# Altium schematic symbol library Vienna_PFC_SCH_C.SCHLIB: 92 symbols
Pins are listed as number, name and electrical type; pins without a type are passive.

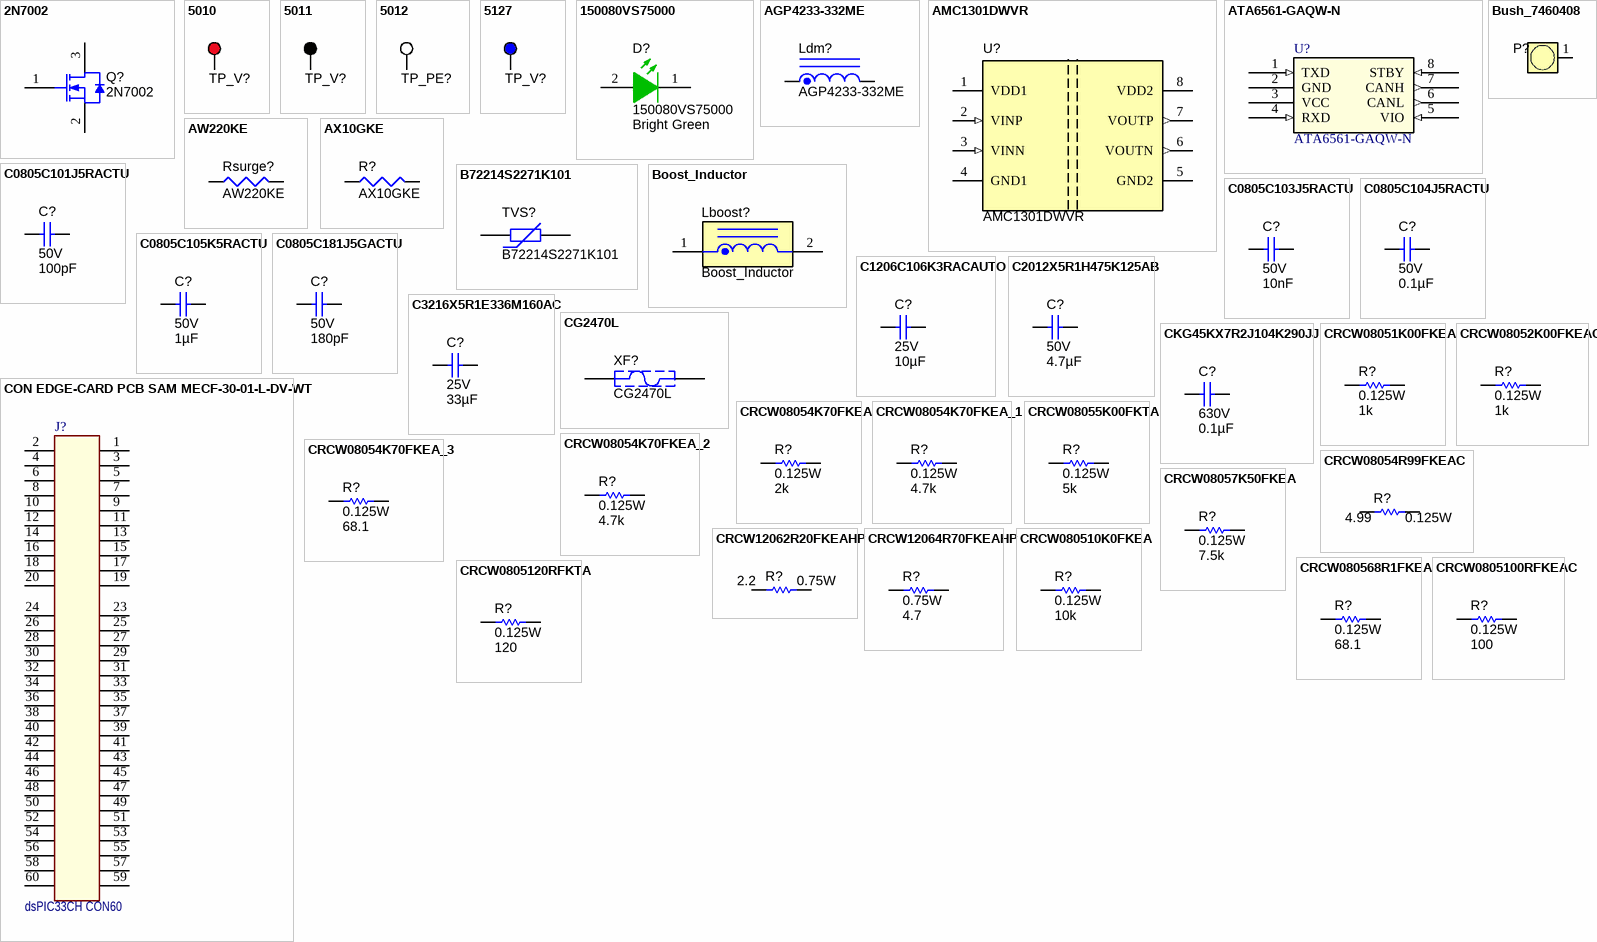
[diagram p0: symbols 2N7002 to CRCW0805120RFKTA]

## 2N7002
designator Q?
MOSFET, N-CH, 60 V, 115 MA, SOT-23; Manufacturer: Fairchild Semiconductor; Alternate Manufacturer: None; U/M: EA; ChType: N; Value: 60V; VdsMax_V: 60; Value1: ? ohm; Value2: ? nC; Vgs_V: 20; IdsMax_A: 115; SizeAreaWB_mm2: 14; SizeArea_mm2: 7.5; SizeX_mm: 2.5; SizeY_mm: 3; SizeZ_mm: 1.1; AEC Category: Q101
footprint SOT-23 (SOT23, 3-Leads, Body 2.9x1.3mm, Pitch 0.95mm, Lead Span 2.5mm, IPC Medium Density)
footprint SOT-23M
footprint SOT-23L
pins: 1 G, 2 S, 3 D

## 5010
designator TP_V?  (value not drawn)
Test Point, Multipurpose, Red, TH; Manufacturer: Keystone; CompType: Test Point Loop; ContactFinish: Silver
footprint Keystone5010 (Keystone Multipurpose loops)
pins: 1

## 5011
designator TP_V?  (value not drawn)
Test Point, Multipurpose, Black, TH; Manufacturer: Keystone; CompType: Test Point Loop; ContactFinish: Silver
footprint Keystone5011 (Keystone Multipurpose loops)
pins: 1

## 5012
designator TP_PE?  (value not drawn)
Test Point, Multipurpose, White, TH; Manufacturer: Keystone; CompType: Test Point Loop; ContactFinish: Silver
footprint Keystone5012 (Keystone Multipurpose loops)
pins: 1

## 5127
designator TP_V?  (value not drawn)
Test Point, Multipurpose, Blue, TH; Manufacturer: Keystone; CompType: Test Point Loop; U/M: EA; ContactFinish: Silver
footprint Keystone5127 (Keystone Multipurpose loops)
pins: 1

## 150080VS75000
designator D?  value Bright Green
LED, Bright Green, SMD; Manufacturer: Wurth Elektronik; SymbolCreator: Altium; Type: AlInGaP; Vf_V: 2; Value2: 2V; Io_A: 0.02; Vr_V: 5; Tjmax_C: 85; Power_TotalModule: 0.072; Value1: 0.072W; Angle: 140; U/M: EA
footprint WL-SMCW_Green_0805 (SMD, 2-Leads, Body 2x1.25mm)
pins: 1 K, 2 A

## AGP4233-332ME
designator Ldm?
FIXED IND 3.3UH 34A  TH, Coilcraft; CompType: Fixed Inductors
footprint AGP4233-332ME (Inductor)
pins: 1, 2

## AMC1301DWVR
designator U?
Precision +/-250-mV Input, 3-us Delay, Reinforced Isolated Amplifier, DWV0008A (SOIC-8); Manufacturer: Texas Instruments; SymbolCreator: Altium; SizeArea_mm2: 67.275; SizeAreaWB_mm2: 105.975; SizeX_mm: 11.5; SizeY_mm: 5.85; SizeZ_mm: 2.8; CompType: IC; U/M: EA
footprint AMC1301 (SOIC, 8-Leads, Body 5.95x7.6mm (max), Pitch 1.27mm)
pins: 1 VDD1 (power), 2 VINP (in), 3 VINN (in), 4 GND1 (power), 5 GND2 (power), 6 VOUTN (out), 7 VOUTP (out), 8 VDD2 (power)

## ATA6561-GAQW-N
designator U?
CAN Interface IC Industrial Grade CAN TRX with VIO PIN (SO8); Manufacturer: Microchip Technology / Atmel; GENERIC_PART_NUMBER: SN65HVD234; INDUSTRY_STD_PKG_TYPE: SOIC; PIN_COUNT: 8; PACKAGE_DESIGNATOR: D; Vendor: Mouser
footprint SOIC8
pins: 1 TXD (in), 2 GND (power), 3 VCC (power), 4 RXD (in), 5 VIO (in), 6 CANL (out), 7 CANH (out), 8 STBY (in)

## AW220KE
designator Rsurge?
RES 22 OHM 2.5W 10% RADIAL; Manufacturer: Ohmite; CompType: Through Hole Resistors
footprint AW220KE (Capacitor)
pins: 1, 2

## AX10GKE
designator R?
RES 1 OHM 3.5W 10% RADIAL; Manufacturer: Ohmite; CompType: Through Hole Resistors
footprint AX10GKE (Res)
pins: 1, 2

## B72214S2271K101
designator TVS?
VARISTOR 430V 6KA DISC 14MM, EPCOS (TDK); CompType: TVS - Varistors, MOVs
footprint B72214S2271K101 (Capacitor)
pins: 1, 2

## Boost_Inductor
designator Lboost?
Boost_Inductor, Handmake
footprint Boost_Inductor
pins: 1, 2

## Bush_7460408
designator P?  (value not drawn)
TERM PWR ELEMENT M5 12 PIN PCB; Manufacturer: Wurth Electronics Inc.
footprint Bush7460408 (Power Connecter 12pin)
pins: 1 (power) "Voltage input"

## C0805C101J5RACTU
designator C?  VDC_V: 50V  ValueDisplayed: 100pF  (hidden comment: C0805C101J5RACTU)
CAP, CERM, 100 pF, 50 V, +/- 5%, X7R, 0805; Manufacturer: Kemet; CompType: Capacitor; Tolerance_%: 5; TaMin_C: -55; TaMax_C: 125; Cap_Case: 0805; AEC Category: Q200
signal-integrity model Cap
simulation model Cap
footprint 0805_HV (0805 with 30mil clearance between pads)
footprint 0805_HV1
footprint 0805
footprint 0805M
footprint 0805L
pins: 1, 2

## C0805C103J5RACTU
designator C?  VDC_V: 50V  ValueDisplayed: 10nF  (hidden comment: C0805C103J5RACTU)
CAP, CERM, 10 nF, 50 V, +/- 5%, X7R, 0805; Manufacturer: Kemet; CompType: Capacitor; Tolerance_%: 5; TaMin_C: -55; TaMax_C: 125; Cap_Case: 0805; AEC Category: Q200
signal-integrity model Cap
simulation model Cap
footprint 0805_HV (0805 with 30mil clearance between pads)
footprint 0805_HV1
footprint 0805
footprint 0805M
footprint 0805L
pins: 1, 2

## C0805C104J5RACTU
designator C?  VDC_V: 50V  ValueDisplayed: 0.1µF  (hidden comment: C0805C104J5RACTU)
CAP, CERM, 0.1 µF, 50 V, +/- 5%, X7R, 0805; Manufacturer: Kemet; CompType: Capacitor; Tolerance_%: 5; TaMin_C: -55; TaMax_C: 125; Cap_Case: 0805; AEC Category: Q200
signal-integrity model Cap
simulation model Cap
footprint 0805_HV (0805 with 30mil clearance between pads)
footprint 0805_HV1
footprint 0805
footprint 0805M
footprint 0805L
pins: 1, 2

## C0805C105K5RACTU
designator C?  VDC_V: 50V  ValueDisplayed: 1µF  (hidden comment: C0805C105K5RACTU)
CAP, CERM, 1 µF, 50 V, +/- 5%, X7R, 0805; Manufacturer: Kemet; CompType: Capacitor; Tolerance_%: 10; TaMin_C: -55; TaMax_C: 125; Cap_Case: 0805; AEC Category: Q200
signal-integrity model Cap
simulation model Cap
footprint 0805_HV (0805 with 30mil clearance between pads)
footprint 0805_HV1
footprint 0805
footprint 0805M
footprint 0805L
pins: 1, 2

## C0805C181J5GACTU
designator C?  VDC_V: 50V  ValueDisplayed: 180pF  (hidden comment: C0805C181J5GACTU)
CAP, CERM, 180 pF, 50 V, +/- 5%, X7R, 0805; Manufacturer: Kemet; CompType: Capacitor; Tolerance_%: 5; TaMin_C: -55; TaMax_C: 125; Cap_Case: 0805; AEC Category: Q200
signal-integrity model Cap
simulation model Cap
footprint 0805_HV (0805 with 30mil clearance between pads)
footprint 0805_HV1
footprint 0805
footprint 0805M
footprint 0805L
pins: 1, 2

## C1206C106K3RACAUTO
designator C?  VDC_V: 25V  ValueDisplayed: 10µF  (hidden comment: C1206C106K3RACAUTO)
CAP, CERM, 10 µF, 25 V, +/- 10%, X7R, 1206_190; Manufacturer: Kemet; Polarized: N; CompType: Capacitor; Value: 10uF; U/M: EA; Cap_F: 0.00001; Tolerance_%: 10; Value1: Unknown; TaMin_C: -55; TaMax_C: 125; Cap_Case: 1206; AEC Category: Q200
signal-integrity model Cap
simulation model Cap
footprint 1206_190
footprint 1206_190M
footprint 1206_190L
pins: 1, 2

## C2012X5R1H475K125AB
designator C?  VDC_V: 50V  ValueDisplayed: 4.7µF  (hidden comment: C2012X5R1H475K125AB)
CAP, CERM, 4.7 µF, 50 V, +/- 10%, X5R, 0805; Manufacturer: TDK; Polarized: N; CompType: Capacitor; Value: 4.7uF; U/M: EA; Cap_F: 0.0000047; Tolerance_%: 10; Value1: Unknown; TaMin_C: -55; TaMax_C: 85; Cap_Case: 0805; AEC Category: Q200
signal-integrity model Cap
simulation model Cap
footprint 0805_HV (0805 with 30mil clearance between pads)
pins: 1, 2

## C3216X5R1E336M160AC
designator C?  VDC_V: 25V  ValueDisplayed: 33µF  (hidden comment: C3216X5R1E336M160AC)
CAP, CERM, 33 µF, 25 V, +/- 20%, X5R, 1206; Manufacturer: TDK; Polarized: N; CompType: Capacitor; Value: 33uF; U/M: EA; Tolerance_%: 20; Value1: Unknown; TaMin_C: -55; TaMax_C: 85; Cap_Case: 1206; AEC Category: Q200
signal-integrity model Cap
simulation model Cap
footprint 1206_190
pins: 1, 2

## CG2470L
designator XF?
GDT 470V 20KA THROUGH HOLE,  Littelfuse Inc.; CompType: Gas Discharge Tube Arresters (GDT)
footprint CG2470L (Capacitor)
pins: 1, 2

## CKG45KX7R2J104K290JJ
designator C?  VDC_V: 630V  ValueDisplayed: 0.1µF  (hidden comment: CKG45KX7R2J104K290JJ)
CAP, CERM, 0.1 µF, 630V, +/- 10%, X7R, 1206; Value: 33uF; Value1: Unknown; AEC Category: Q200
signal-integrity model Cap
simulation model Cap
footprint 1812 (SMD, 2-Leads, Body 4.8x3.4mm)
pins: 1, 2

## CON EDGE-CARD PCB SAM MECF-30-01-L-DV-WT
designator J?  value dsPIC33CH CON60  (hidden comment: CON EDGE-CARD PCB SAM MECF-30-01-L-DV-WT)  (no BOM)
Get it already; MCHP-ID: CON1706; Dev Tools Status: Design; Owner: Tim Moffat; Populated: YES
footprint MC_dsPIC33CH_CON60
footprint HDR_F_1.27_2X30_V_SMD_MECF-30-01-L-DV-WT
pins: 1, 2, 3, 4, 5, 6, 7, 8, 9, 10, 11, 12, 13, 14, 15, 16, 17, 18, 19, 20, 23, 24, 25, 26, 27, 28, 29, 30, 31, 32, 33, 34, 35, 36, 37, 38, 39, 40, 41, 42, 43, 44, 45, 46, 47, 48, 49, 50, 51, 52, 53, 54, 55, 56, 57, 58, 59, 60

## CRCW08051K00FKEA
designator R?  Value2: 0.125W  ValueDisplayed: 1k  (hidden comment: CRCW08051K00FKEA)
RES, 1 k, 1%, 0.125 W, 0805; Manufacturer: Vishay-Dale; CompType: Resistor; Value: 1k; Value_Code: 1kR; Tolerance_%: 1; Power_W: 0.125; VDC_V: 150; TempCo: 100 ppm/C; EIA_Code: E96; U/M: EA; AEC Category: Q200
signal-integrity model Resistor
simulation model Resistor
footprint 0805_HV (0805 with 30mil clearance between pads)
footprint 0805_HV1
footprint 0805
footprint 0805M
pins: 1, 2

## CRCW08052K00FKEAC
designator R?  Value2: 0.125W  ValueDisplayed: 1k  (hidden comment: CRCW08052K00FKEAC)
RES, 2K, 1%, 0.125 W, 0805; Manufacturer: Vishay-Dale; CompType: Resistor; Value: 348; Tolerance_%: 1; Power_W: 0.125; VDC_V: 150; TempCo: 100 ppm/C; EIA_Code: E96; U/M: EA; AEC Category: Q200
signal-integrity model Resistor
simulation model Resistor
footprint 0805_HV (0805 with 30mil clearance between pads)
footprint 0805_HV1
footprint 0805
footprint 0805M
pins: 1, 2

## CRCW08054K70FKEA
designator R?  Value2: 0.125W  ValueDisplayed: 2k  (hidden comment: CRCW08054K70FKEA)
RES, 4.7K, 1%, 0.125 W, 0805; Manufacturer: Vishay-Dale; CompType: Resistor; Value: 348; Tolerance_%: 1; Power_W: 0.125; VDC_V: 150; TempCo: 100 ppm/C; EIA_Code: E96; U/M: EA; AEC Category: Q200
signal-integrity model Resistor
simulation model Resistor
footprint 0805_HV (0805 with 30mil clearance between pads)
footprint 0805_HV1
footprint 0805
footprint 0805M
pins: 1, 2

## CRCW08054K70FKEA_1
designator R?, comment Value2: 0.125W  ValueDisplayed: 4.7k  (hidden comment: CRCW08054K70FKEA)
RES, 4.7K, 1%, 0.125 W, 0805; Manufacturer: Vishay-Dale; CompType: Resistor; Tolerance_%: 1; Power_W: 0.125; VDC_V: 150; TempCo: 100 ppm/C; EIA_Code: E96; U/M: EA; AEC Category: Q200
signal-integrity model Resistor
simulation model Resistor
footprint 0805_HV (0805 with 30mil clearance between pads)
footprint 0805_HV1
footprint 0805
footprint 0805M
pins: 1, 2

## CRCW08054K70FKEA_2
designator R?, comment Value2: 0.125W  ValueDisplayed: 4.7k  (hidden comment: CRCW080510K0FKEA)
RES, 4.7K, 1%, 0.125 W, 0805; PartNumber: CRCW08054K70FKEA; Manufacturer: Vishay-Dale; CompType: Resistor; Tolerance_%: 1; Power_W: 0.125; VDC_V: 150; TempCo: 100 ppm/C; EIA_Code: E96; U/M: EA; AEC Category: Q200
signal-integrity model Resistor
simulation model Resistor
footprint 0805_HV (0805 with 30mil clearance between pads)
footprint 0805_HV1
footprint 0805
footprint 0805M
pins: 1, 2

## CRCW08054K70FKEA_3
designator R?, comment Value2: 0.125W  ValueDisplayed: 68.1  (hidden comment: ERJ-6ENF68R1V)
RES SMD 68.1 OHM 1% 1/8W 0805; Manufacturer: Vishay-Dale; CompType: Resistor; Value: 68.1; Tolerance_%: 1; Power_W: 0.125; VDC_V: 150; TempCo: 100 ppm/C; EIA_Code: E96; U/M: EA; AEC Category: Q200
signal-integrity model Resistor
simulation model Resistor
footprint 0805_HV (0805 with 30mil clearance between pads)
footprint 0805_HV1
footprint 0805
footprint 0805M
pins: 1, 2

## CRCW08054R99FKEAC
designator R?  Value2: 0.125W  ValueDisplayed: 4.99  (hidden comment: CRCW08054R99FKEAC)
RES, 4.99 1%, 0.125 W, 0805; Manufacturer: Vishay-Dale; CompType: Resistor; Value: 4.99; Value_Code: 4R99; Tolerance_%: 1; Power_W: 0.125; VDC_V: 150; TempCo: 100 ppm/C; SizeArea_mm2: 2.5; SizeX_mm: 2; SizeY_mm: 1.25; SizeZ_mm: 1.45; EIA_Code: E24; U/M: EA; AEC Category: Q200
signal-integrity model Resistor
simulation model Resistor
footprint 0805_HV (0805 with 30mil clearance between pads)
footprint 0805_HV1
footprint 0805
footprint 0805M
footprint 0805L
pins: 1, 2

## CRCW08055K00FKTA
designator R?  Value2: 0.125W  ValueDisplayed: 5k  (hidden comment: CRCW08055K00FKTA)
RES, 5K, 1%, 0.125 W, 0805; Manufacturer: Vishay-Dale; CompType: Resistor; Tolerance_%: 1; Power_W: 0.125; VDC_V: 150; TempCo: 100 ppm/C; EIA_Code: E96; U/M: EA; AEC Category: Q200
signal-integrity model Resistor
simulation model Resistor
footprint 0805_HV (0805 with 30mil clearance between pads)
footprint 0805_HV1
footprint 0805
footprint 0805M
pins: 1, 2

## CRCW08057K50FKEA
designator R?  Value2: 0.125W  ValueDisplayed: 7.5k  (hidden comment: CRCW08057K50FKEA)
RES, 7.5K, 1%, 0.125 W, 0805; Manufacturer: Vishay-Dale; CompType: Resistor; Value: 348; Tolerance_%: 1; Power_W: 0.125; VDC_V: 150; TempCo: 100 ppm/C; EIA_Code: E96; U/M: EA; AEC Category: Q200
signal-integrity model Resistor
simulation model Resistor
footprint 0805_HV (0805 with 30mil clearance between pads)
footprint 0805_HV1
footprint 0805
footprint 0805M
pins: 1, 2

## CRCW12062R20FKEAHP
designator R?, comment Value2: 0.75W  ValueDisplayed: 2.2  (hidden comment: CRCW12064R70FKEAHP)
RES, 2.2, 1%, 0.75 W, 1206; Manufacturer: Vishay-Dale; CompType: Resistor; Value: 2.2; Value_Code: 2R2; Tolerance_%: 1; Power_W: 0.75; VDC_V: 200V; TempCo: 100 ppm/C; U/M: EA; AEC Category: Q200
signal-integrity model Resistor
simulation model Resistor
footprint 1206_190
footprint 0805_HV1
footprint 0805
footprint 0805M
pins: 1, 2

## CRCW12064R70FKEAHP
designator R?, comment Value2: 0.75W  ValueDisplayed: 4.7  (hidden comment: CRCW12062R20FKEAHP)
RES, 4.7, 1%, 0.75 W, 1206; Manufacturer: Vishay-Dale; CompType: Resistor; Value: 4.7; Value_Code: 4R7; Tolerance_%: 1; Power_W: 0.75; VDC_V: 200V; TempCo: 100 ppm/C; U/M: EA; AEC Category: Q200
signal-integrity model Resistor
simulation model Resistor
footprint 1206_190
footprint 0805_HV1
footprint 0805
footprint 0805M
pins: 1, 2

## CRCW080510K0FKEA
designator R?  Value2: 0.125W  ValueDisplayed: 10k  (hidden comment: CRCW080510K0FKEA)
RES, 10K, 1%, 0.125 W, 0805; Manufacturer: Vishay-Dale; CompType: Resistor; Tolerance_%: 1; Power_W: 0.125; VDC_V: 150; TempCo: 100 ppm/C; EIA_Code: E96; U/M: EA; AEC Category: Q200
signal-integrity model Resistor
simulation model Resistor
footprint 0805_HV (0805 with 30mil clearance between pads)
footprint 0805_HV1
footprint 0805
footprint 0805M
pins: 1, 2

## CRCW080568R1FKEA
designator R?  Value2: 0.125W  ValueDisplayed: 68.1  (hidden comment: CRCW080568R1FKEA)
RES, 68.1, 1%, 0.125 W, 0805; Manufacturer: Vishay-Dale; CompType: Resistor; Value: 348; Value_Code: 68R1; Tolerance_%: 1; Power_W: 0.125; VDC_V: 150; TempCo: 100 ppm/C; EIA_Code: E96; U/M: EA; AEC Category: Q200
signal-integrity model Resistor
simulation model Resistor
footprint 0805_HV (0805 with 30mil clearance between pads)
footprint 0805_HV1
footprint 0805
footprint 0805M
pins: 1, 2

## CRCW0805100RFKEAC
designator R?  Value2: 0.125W  ValueDisplayed: 100  (hidden comment: CRCW0805100RFKEAC)
RES, 100, 1%, 0.125 W, 0805; Manufacturer: Vishay-Dale; CompType: Resistor; Value: 348; Value_Code: 100R; Tolerance_%: 1; Power_W: 0.125; VDC_V: 150; TempCo: 100 ppm/C; EIA_Code: E96; U/M: EA; AEC Category: Q200
signal-integrity model Resistor
simulation model Resistor
footprint 0805_HV (0805 with 30mil clearance between pads)
footprint 0805_HV1
footprint 0805
footprint 0805M
pins: 1, 2

## CRCW0805120RFKTA
designator R?  Value2: 0.125W  ValueDisplayed: 120  (hidden comment: CRCW0805120RFKTA)
RES, 120, 1%, 0.125 W, 0805; Manufacturer: Vishay-Dale; CompType: Resistor; Value: 120; Value_Code: 120R; Tolerance_%: 1; Power_W: 0.125; VDC_V: 150; TempCo: 100 ppm/C; EIA_Code: E96; U/M: EA; AEC Category: Q200
signal-integrity model Resistor
simulation model Resistor
footprint 0805_HV (0805 with 30mil clearance between pads)
footprint 0805_HV1
footprint 0805
footprint 0805M
pins: 1, 2

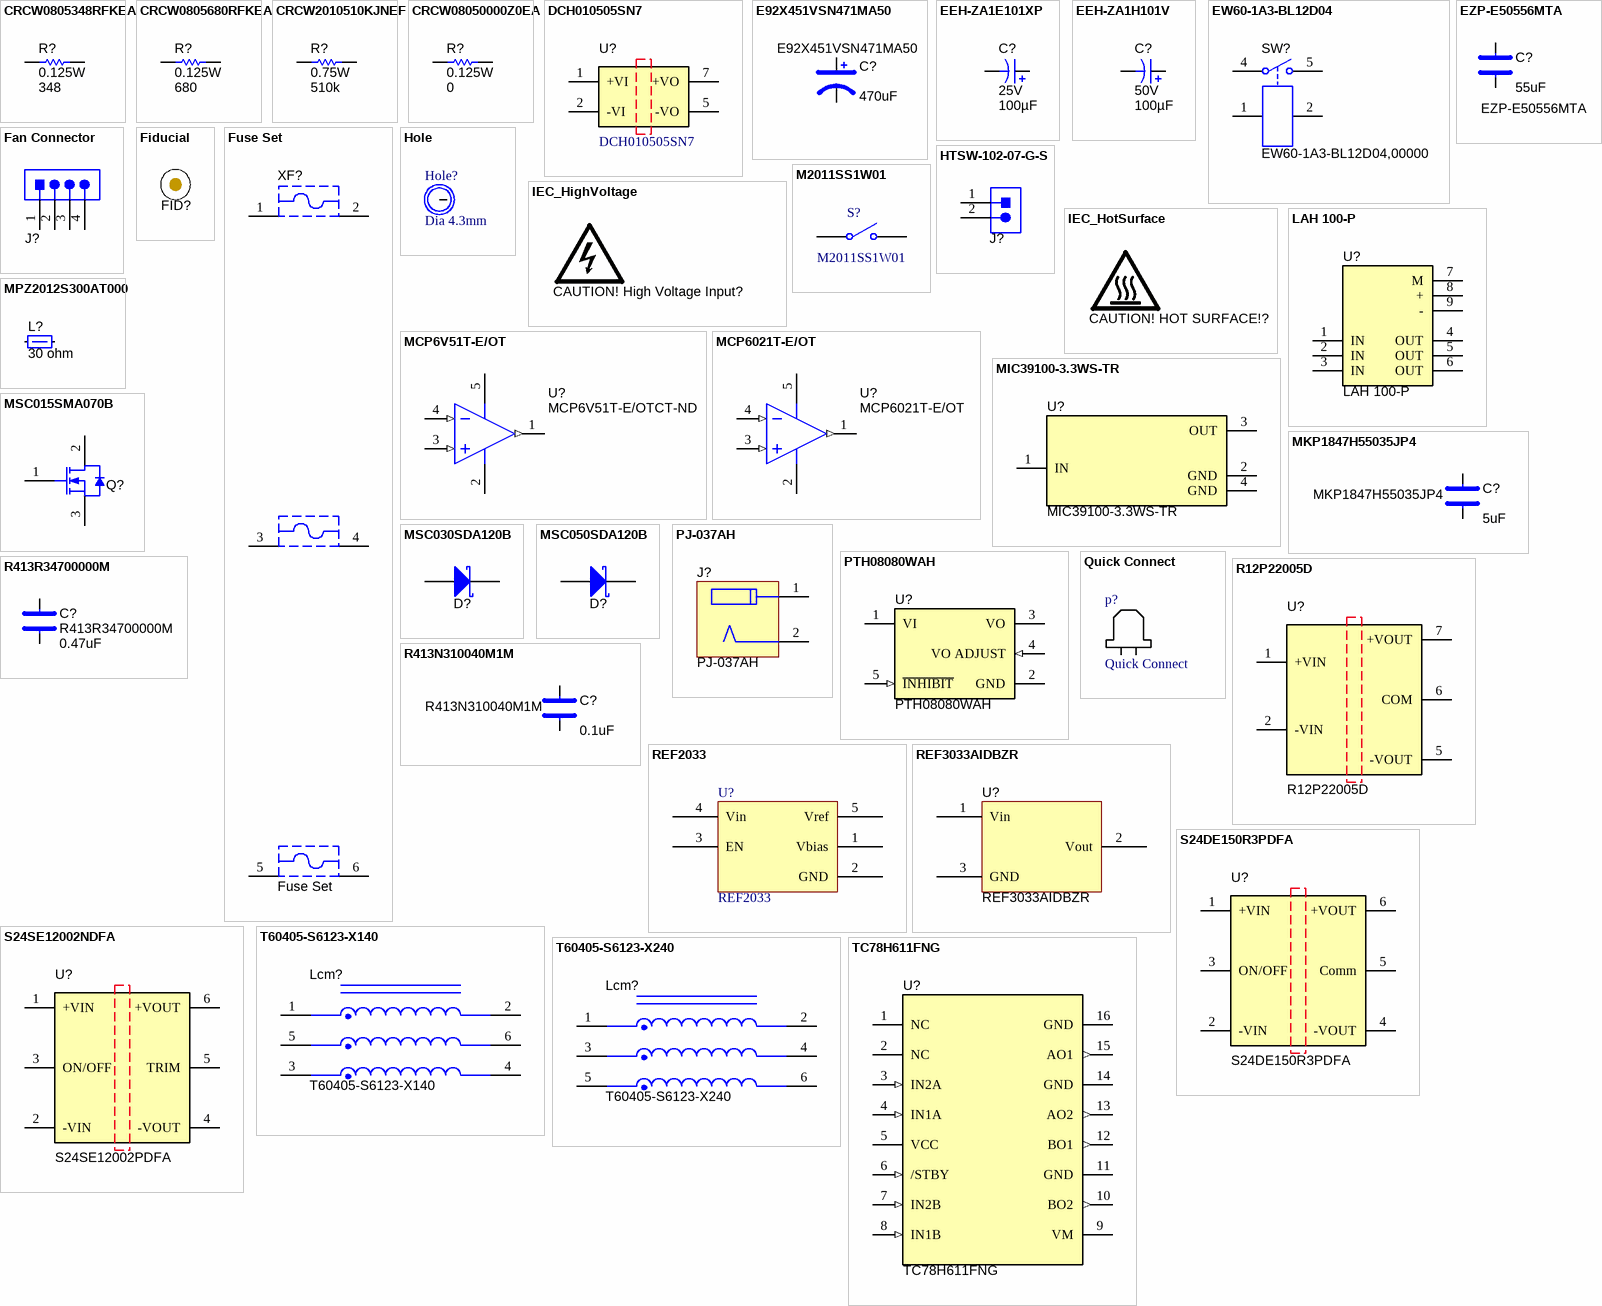
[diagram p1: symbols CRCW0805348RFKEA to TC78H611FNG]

## CRCW0805348RFKEA
designator R?  Value2: 0.125W  ValueDisplayed: 348  (hidden comment: CRCW0805348RFKEA)
RES, 348, 1%, 0.125 W, 0805; Manufacturer: Vishay-Dale; CompType: Resistor; Value: 348; Value_Code: 348R; Tolerance_%: 1; Power_W: 0.125; VDC_V: 150; TempCo: 100 ppm/C; EIA_Code: E96; U/M: EA; AEC Category: Q200
signal-integrity model Resistor
simulation model Resistor
footprint 0805_HV (0805 with 30mil clearance between pads)
footprint 0805_HV1
footprint 0805
footprint 0805M
pins: 1, 2

## CRCW0805680RFKEA
designator R?  Value2: 0.125W  ValueDisplayed: 680  (hidden comment: CRCW0805680RFKEA)
RES, 680, 1%, 0.125 W, 0805; Manufacturer: Vishay-Dale; CompType: Resistor; Value: 680; Res_ohm: 348; Value_Code: 680R; Tolerance_%: 1; Power_W: 0.125; VDC_V: 150; TempCo: 100 ppm/C; EIA_Code: E96; U/M: EA; AEC Category: Q200
signal-integrity model Resistor
simulation model Resistor
footprint 0805_HV (0805 with 30mil clearance between pads)
footprint 0805_HV1
footprint 0805
footprint 0805M
pins: 1, 2

## CRCW2010510KJNEF
designator R?  Value2: 0.75W  ValueDisplayed: 510k  (hidden comment: CRCW2010510KJNEF)
RES, 510 k, 5%, 0.75 W, AEC-Q200 Grade 0, 2010; Manufacturer: Vishay-Dale; CompType: Resistor; Value: 510k; Res_ohm: 510000; Tolerance_%: 5; Power_W: 0.75; VDC_V: 400; TempCo: 200 ppm/C; SizeArea_mm2: 12.5; SizeY_mm: 2.5; SizeZ_mm: 1.66; EIA_Code: E24; U/M: EA; AEC Category: Q200; AEC Qualified: Y; AEC Grade: 0
signal-integrity model Resistor
simulation model Resistor
footprint 2010 (Chip Capacitor, Body 5.08x2.54mm, IPC Medium Density)
footprint 2010M
footprint 2010L
pins: 1, 2

## CRCW08050000Z0EA
designator R?  Value2: 0.125W  ValueDisplayed: 0  (hidden comment: CRCW08050000Z0EA)
RES, 0, 5%, 0.125 W, 0805; Manufacturer: Vishay-Dale; CompType: Resistor; Value: 0; Tolerance_%: 5; Power_W: 0.125; VDC_V: 150; TempCo: 200 ppm/C; EIA_Code: E24; U/M: EA; AEC Category: Q200
signal-integrity model Resistor
simulation model Resistor
footprint 0805_HV (0805 with 30mil clearance between pads)
pins: 1, 2

## DCH010505SN7
designator U?
Miniature, 1 W, 3 kVDC Isolated DC-DC Converter, -40 to 85 degC, 4-pin Module (EDJ4), Pb-Free (RoHS); Manufacturer: Texas Instruments; Alternate PartNumber: Equivalent; Iout(Max)(A): 0.2; Regulated Outputs(#): 1; SubFamily: 1 W & 2 W Miniature; Vin(Max)(V): 5.5; Vin(Min)(V): 4.5
footprint DCH010505SN7 (Module, 4-Leads, Body 19.56x7.62mm)
pins: 1 +VI (power) "Voltage input", 2 -VI (power) "Input side common", 5 -VO (power) "-Voltage out", 7 +VO (power) "+Voltage out"

## E92X451VSN471MA50
designator C?  value 470uF
Aluminum Electrolytic Capacitors - Snap In 450V 470uF 20% Long Life; Manufacturer: United Chemi-Con (UCC)
footprint E92X451VSN471MA50 (Capacitor)
pins: 1, 2

## EEH-ZA1E101XP
designator C?  VDC_V: 25V  ValueDisplayed: 100µF  (hidden comment: EEH-ZA1E101XP)
CAP, Polymer Hybrid, 100 µF, 25 V, +/- 20%, 30 ohm, 6.3x7.7 SMD; Manufacturer: Panasonic; Polarized: Y; CompType: Capacitor; Value: 100uF; U/M: EA; Cap_F: 0.0001; Tolerance_%: 20; Value1: 30 ohm; ESR_ohm: 30; IRMS_A: 2; TaMin_C: -55; TaMax_C: 105; AEC Category: Q200
signal-integrity model Cap
simulation model Cap
footprint SM_RADIAL_6.3BMM (Nichicon 6.3x7.7)
pins: 1 +, 2 -

## EEH-ZA1H101V
designator C?  VDC_V: 50V  ValueDisplayed: 100µF  (hidden comment: EEH-ZA1H101V)
CAP, Polymer Hybrid, 100 µF, 50 V, +/- 20%, 30 ohm, 6.3x7.7 SMD; Manufacturer: Panasonic; Polarized: Y; CompType: Capacitor; Value: 100uF; U/M: EA; Cap_F: 0.0001; Tolerance_%: 20; Value1: 30 ohm; ESR_ohm: 30; IRMS_A: 2; TaMin_C: -55; TaMax_C: 105; AEC Category: Q200
signal-integrity model Cap
simulation model Cap
footprint SM_RADIAL_10BMM (Nichicon 10x10.5)
pins: 1 +, 2 -

## EW60-1A3-BL12D04
designator SW?, comment EW60-1A3-BL12D04,00000
RELAY GEN PURPOSE SPST 60A 12V; Manufacturer: TE Connectivity Potter & Brumfield Relays; CompType: Power Relays
footprint EW60-1A3-BL12D04,00000 (Capacitor)
pins: 1, 2, 4, 5

## EZP-E50556MTA
designator C?  value 55uF
CAP FILM 55UF 10% 500VDC RAD 4LD; Manufacturer: Panasonic Electronic Components; CompType: Film Capacitors
footprint EZP-E50556MTA (Capacitor)
pins: 1, 2

## Fan Connector
designator J?  (value not drawn)
4 Positions Header Connector 0.100" (2.54mm) Through Hole Tin; Manufacturer: TE Connectivity AMP Connectors
footprint Fan Connector
pins: 1 GND_BLACK, 2 +VCC_RED, 3 SENSE_YELLOW, 4 CONTROL_BLUE
1 alternate drawing of the same symbol

## Fiducial
designator FID?  (value not drawn)
Fiducial mark.  There is nothing to buy or mount.; SymbolCreator: codlsc
footprint Fiducial10-30
footprint Fiducial10-20
footprint Fiducial15-30
footprint Fiducial20-40
footprint Fiducial6.4-20

## Fuse Set
designator XF?
6*5591-52-R, 3*50C14X51AM
footprint FuseHolde_Set
pins: 1, 2, 3, 4, 5, 6

## Hole
designator Hole?, comment Dia 4.3mm
Hole  Dia 4.3mm
footprint Hole-Dia 4.3mm
pins: 0

## HTSW-102-07-G-S
designator J?  (value not drawn)
Header, 100mil, 2x1, Gold, TH; Manufacturer: Samtec; SymbolCreator: a0412235
footprint Samtec_HTSW-102-07-G-S (Samtec 100mil, 1x2, 230 mil above insulator)
pins: 1, 2
1 alternate drawing of the same symbol

## IEC_HighVoltage
designator CAUTION! High Voltage Input?, comment DANGER HIGH VOLTAGE  (value not drawn)  (no BOM)
IEC 61010-1 High Voltage Warning; SymbolCreator: a0412235
footprint IEC_HighVoltage_Large
footprint IEC_HighVoltage_Medium
footprint IEC_HighVoltage_Small

## IEC_HotSurface
designator CAUTION! HOT SURFACE!?, comment CAUTION HOT SURFACE  (value not drawn)  (no BOM)
IEC 61010-1 Hot Surface Warning; SymbolCreator: a0412235
footprint IEC_HotSurface_Large
footprint IEC_HotSurface_Medium
footprint IEC_HotSurface_Small

## LAH 100-P
designator U?
SENSOR CURRENT HALL 100A AC/DC; Manufacturer: LEM USA Inc.; CompType: Current Transducers
footprint LAH 100-P (Inductor)
pins: 1 IN, 2 IN, 3 IN, 4 OUT, 5 OUT, 6 OUT, 7 M (power), 8 + (power), 9 -

## M2011SS1W01
designator S?
PartNumber: M2011SS1W01/CUL; Manufacturer: NKK Switches
footprint M2011SS1W01 (Capacitor)
pins: 2 COMMON, 3 NO

## MCP6V51T-E/OT
designator U?, comment MCP6V51T-E/OTCT-ND
SINGLE, 45V ZERO-DRIFT OP AMP, E; Alternate Manufacturer: Microchip Technology
footprint OPA192 (SOT23, 5-Leads, Body 2.9x1.6mm, Pitch 0.95mm, Lead Span 2.8mm, IPC Medium Density)
footprint DBV0005A_L (SOT23, 5-Leads, Body 2.9x1.6mm, Pitch 0.95mm, IPC Low Density)
footprint DBV0005A_M (SOT23, 5-Leads, Body 2.9x1.6mm, Pitch 0.95mm, IPC Low Density)
pins: 1 OUT (out), 2 V- (power), 3 IN+ (in), 4 IN- (in), 5 V+ (power)

## MCP6021T-E/OT
designator U?
General Purpose Amplifier 1 Circuit Rail-to-Rail SOT-23-5; Manufacturer: Microchip Technology; Number of Channels: 2; Offset Drift(Typ)(uV/C): 1.5; Total Supply Voltage(Max)(+5V is 5, +/-5V is 10): 5.5; Total Supply Voltage(Min)(+5V is 5, +/-5V is 10): 2.5
footprint OPA320 (SOT23, 5-Leads, Body 2.9x1.6mm, Pitch 0.95mm, Lead Span 2.8mm, IPC Medium Density)
footprint DBV0005A_L (SOT23, 5-Leads, Body 2.9x1.6mm, Pitch 0.95mm, IPC Low Density)
footprint DBV0005A_M (SOT23, 5-Leads, Body 2.9x1.6mm, Pitch 0.95mm, IPC Low Density)
pins: 1 OUT (out), 2 V- (power), 3 IN+ (in), 4 IN- (in), 5 V+ (power)

## MIC39100-3.3WS-TR
designator U?
Linear Voltage Regulator IC  1 Output  1A SOT-223; Manufacturer: Microchip Technology
footprint TLV1117 (SOT223/SC73, 4-Leads, Body 6.5x3.5mm, Pitch 2.3mm, Lead Span 7mm, IPC Medium Density)
footprint DCY0004A_M
footprint DCY0004A_L
pins: 1 IN (power), 2 GND (power), 3 OUT (power), 4 GND (power)

## MKP1847H55035JP4
designator C?  value 5uF
CAP FILM 5UF 5% 700VDC RAD 4LDS; Manufacturer: Vishay BC Components; CompType: Film Capacitors
footprint MKP1847H55035JP4 (Capacitor)
pins: 1, 2

## MPZ2012S300AT000
designator L?  value 30 ohm  (hidden comment: MPZ2012S300AT000)
Ferrite Bead, 30 ohm @ 100 MHz, 6 A, 0805; Manufacturer: TDK; Imax_A: 6; DCR_ohm: 0.01; Value1: 0.01 ohm; Value2: 6A; ZTyp@100MHz_Ohm: 30
footprint 0805_HV (0805 with 30mil clearance between pads)
footprint 0805_HV1
footprint 0805
footprint 0805M
footprint 0805L
pins: 1, 2

## MSC015SMA070B
designator Q?  (value not drawn)
GEN2 SIC MOSFET 700V 15MOHM TO-247-3; Manufacturer: Microsemi Corporation; CompType: Transistors - FETs, MOSFETs - Single
footprint TO-247
pins: 1 G, 2 D, 3 S

## MSC030SDA120B
designator D?  (value not drawn)
DIODE SCHOTTKY 1.2KV 30A TO247; Manufacturer: Microsemi Corporation; CompType: Diodes - Rectifiers - Single
footprint TO-247-ress
pins: 1 K, 2 A

## MSC050SDA120B
designator D?  (value not drawn)
DIODE SCHOTTKY 1.2KV 50A TO247; Manufacturer: Microsemi Corporation; CompType: Diodes - Rectifiers - Single
footprint TO-247-ress
pins: 1 K, 2 A

## PJ-037AH
designator J?
Power Jack, 2mm, R/A, TH; Manufacturer: CUI Inc.; SymbolCreator: Altium; Pitch_mm: 6; Gender: Male; Shrouded: N; Row_Count: 1
footprint PJ-037AH (Power Jack, 2mm, R/A, TH)
pins: 1, 2

## PTH08080WAH
designator U?
2.25 A, 4.5 to 18 V Input Wide Adjust Miniature Power Module, -40 to 85 degC, 5-pin Module (EUF5), Pb-Free (RoHS); Manufacturer: Texas Instruments; Alternate PartNumber: Equivalent; Iout(Max)(A): 2.25; Regulated Outputs(#): 1; SubFamily: Non-Isolated POL; Vin(Max)(V): 18; Vin(Min)(V): 4.5; VO Adjustable: TRUE; Vout(Max)(V): 5.5; Vout(Min)(V): 0.9
footprint PTH08080WAH
pins: 1 VI (power) "The positive input voltage power node to the module, which is referenced to common GND.", 2 GND (power) "This is the common ground connection for the VI and VO power connections. It is also the 0-Vdc reference for the Inhibit and VO Adjust control inputs.", 3 VO (power) "The regulated positive power output with respect to the GND node.", 4 VO ADJUST (in) "A 1% resistor must be connected between this pin and GND (pin 1) to set the output voltage of the module higher than 0.9 V. If left open-circuit, the output voltage defaults to this value. The temperature stability of the (See Datasheet)", 5 ~{INHIBIT} (in) "The Inhibit pin is an open-collector/drain-negative logic input that is referenced to GND. Applying a low-level ground signal to this input disables the module's output. When the Inhibit control is active, the input current (See Datasheet)"

## Quick Connect
designator p?
0.187" (4.75mm) Quick Connect Male Solder
footprint Quick Connect-4.75mm
pins: 1, 1

## R12P22005D
designator U?
CONV DC/DC 2W 12VIN +20/-5VOUT T; Manufacturer: Recom Power; CompType: DC DC Converters
footprint R12P22005D
pins: 1 +VIN, 2 -VIN, 5 -VOUT, 6 COM, 7 +VOUT

## R413N310040M1M
designator C?  value 0.1uF
CAP FILM 0.1UF 20% 1KVDC RADIAL; Manufacturer: KEMET; CompType: Film Capacitors
footprint R413N310040M1M (Capacitor)
pins: 1, 2

## R413R34700000M
designator C?  value 0.47uF
CAP FILM 0.47UF 20% 1KVDC RADIAL; Manufacturer: KEMET; CompType: Film Capacitors
footprint R413R34700000M (Capacitor)
pins: 1, 2

## REF2033
designator U?
IC VREF SERIES 1.65V/3.3V 5SOT; PartNumber: REF2033AIDDCR; Manufacturer: Texas Instruments
footprint REF2033
pins: 1 Vbias, 2 GND, 3 EN, 4 Vin, 5 Vref

## REF3033AIDBZR
designator U?
IC VREF SERIES 3.3V SOT23-3; Manufacturer: Texas Instruments; Number of Channels: 2
footprint SOT-23 (SOT23, 3-Leads, Body 2.9x1.3mm, Pitch 0.95mm, Lead Span 2.5mm, IPC Medium Density)
footprint DBV0005A_L (SOT23, 5-Leads, Body 2.9x1.6mm, Pitch 0.95mm, IPC Low Density)
footprint DBV0005A_M (SOT23, 5-Leads, Body 2.9x1.6mm, Pitch 0.95mm, IPC Low Density)
pins: 1 Vin, 2 Vout, 3 GND

## S24DE150R3PDFA
designator U?
DC/DC CONVERT +/-15V 330MA 6DIP; Manufacturer: Delta Electronics; CompType: DC DC Converters
footprint S24SE12002NDFA
pins: 1 +VIN, 2 -VIN, 3 ON/OFF, 4 -VOUT, 5 Comm, 6 +VOUT

## S24SE12002NDFA
designator U?, comment S24SE12002PDFA
DC/DC CONVERTER 12V 1.67A 6DIP; Manufacturer: Delta Electronics; CompType: DC DC Converters
footprint S24SE12002NDFA
pins: 1 +VIN, 2 -VIN, 3 ON/OFF, 4 -VOUT, 5 TRIM, 6 +VOUT

## T60405-S6123-X140
designator Lcm?
Common Mode Chokes / Filters 580 uH 40A horiz. 2.5mH; Manufacturer: Vacuumschmelze
footprint T60405-S6123-X140 (Common mode choke)
pins: 1, 2, 3, 4, 5, 6

## T60405-S6123-X240
designator Lcm?
Common Mode Chokes / Filters CM Choke 3 phase 40A horiz. 1.5mH; Manufacturer: Vacuumschmelze
footprint T60405-S6123-X240 (Common mode choke)
pins: 1, 2, 3, 4, 5, 6

## TC78H611FNG
designator U?
BRUSHED MOTOR DRIVER IC 2-CHANNE; Manufacturer: Toshiba Semiconductor and Storage
footprint TSSOP16_small pins (SOP, 16-Leads, Body 6.2x5.3mm, Pitch 0.65mm, IPC Medium Density)
footprint D0008B_N
footprint D0008B_M
footprint D0008B_L
pins: 1 NC (power), 2 NC (power), 3 IN2A (in), 4 IN1A (in), 5 VCC (power), 6 /STBY (in), 7 IN2B (in), 8 IN1B (in), 9 VM (power), 10 BO2 (out), 11 GND (power), 12 BO1 (out), 13 AO2 (out), 14 GND (power), 15 AO1 (out), 16 GND (power)

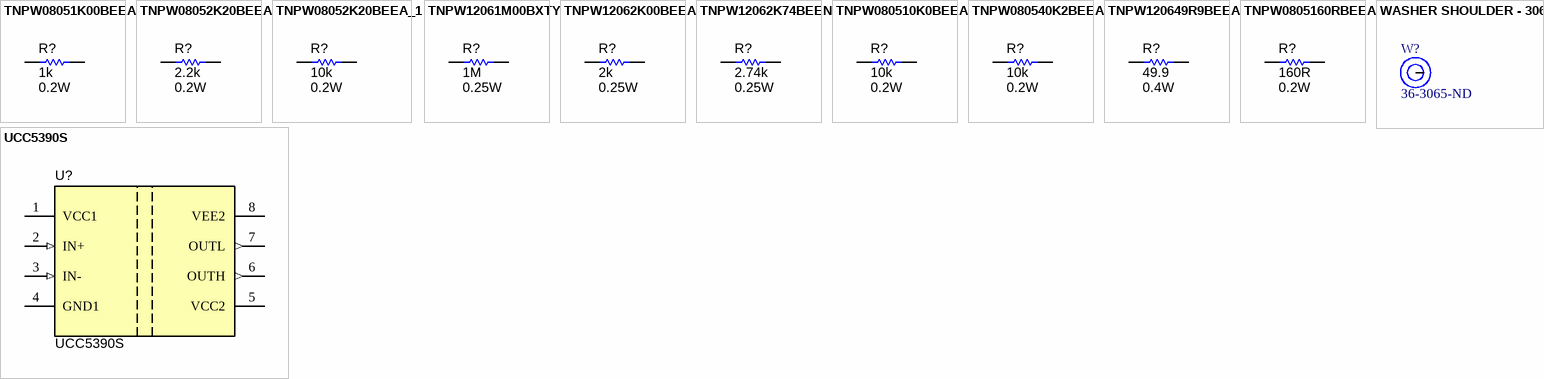
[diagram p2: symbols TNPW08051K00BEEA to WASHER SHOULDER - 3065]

## TNPW08051K00BEEA
designator R?  value 1k  Power_W: 0.2W
RES 1K OHM 0.1% 1/5W 0805; Manufacturer: Vishay; CompType: Resistor; Tolerance_%: 0.1; VDC_V: 200V; TempCo: 25ppm/C; AEC Category: Q200
signal-integrity model Resistor
simulation model Resistor
footprint 0805_HV (0805 with 30mil clearance between pads)
footprint 2010M
footprint 2010L
pins: 1, 2

## TNPW08052K20BEEA
designator R?  value 2.2k  Power_W: 0.2W  (hidden comment: TNPW08052K20BEEA)
RES 2.2K OHM 0.1% 1/5W 0805; Manufacturer: Vishay; CompType: Resistor; Tolerance_%: 0.1; VDC_V: 200V; TempCo: 25ppm/C; AEC Category: Q200
signal-integrity model Resistor
simulation model Resistor
footprint 0805_HV (0805 with 30mil clearance between pads)
footprint 2010M
footprint 2010L
pins: 1, 2

## TNPW08052K20BEEA_1
designator R?, comment value 10k  Power_W: 0.2W  (hidden comment: TNPW08052K20BEEA)
RES 2.2K OHM 0.1% 1/5W 0805; Manufacturer: Vishay; CompType: Resistor; Tolerance_%: 0.1; VDC_V: 200V; TempCo: 25ppm/C; AEC Category: Q200
signal-integrity model Resistor
simulation model Resistor
footprint 0805_HV (0805 with 30mil clearance between pads)
footprint 2010M
footprint 2010L
pins: 1, 2

## TNPW12061M00BXTY
designator R?  value 1M  Power_W: 0.25W  (hidden comment: TNPW12061M00BXTY)
RES, 1 M, 0.1%, 0.25 W, 15 PPM / C, AEC-Q200; Manufacturer: Vishay; CompType: Resistor; Tolerance_%: 0.1; VDC_V: 200V; AEC Category: Q200
signal-integrity model Resistor
simulation model Resistor
footprint 1206_190
footprint 2010M
footprint 2010L
pins: 1, 2

## TNPW12062K00BEEA
designator R?  value 2k  Power_W: 0.25W  (hidden comment: TNPW12062K00BEEA)
RES, 2 k,  0.1%, 0.25 W, 25 PPM / C, AEC-Q200; Manufacturer: Vishay; CompType: Resistor; Tolerance_%: 0.1; VDC_V: 200V; AEC Category: Q200
signal-integrity model Resistor
simulation model Resistor
footprint 1206_190
footprint 2010M
footprint 2010L
pins: 1, 2

## TNPW12062K74BEEN
designator R?  value 2.74k  Power_W: 0.25W  (hidden comment: TNPW12062K74BEEN)
RES, 2.74 k,  0.1%, 0.25 W, 25 PPM / C, AEC-Q200; Manufacturer: Vishay; CompType: Resistor; Tolerance_%: 0.1; VDC_V: 200V; AEC Category: Q200
signal-integrity model Resistor
simulation model Resistor
footprint 1206_190
footprint 2010M
footprint 2010L
pins: 1, 2

## TNPW080510K0BEEA
designator R?  value 10k  Power_W: 0.2W  (hidden comment: TNPW080510K0BEEA)
RES 10K OHM 0.1% 1/5W 0805; Manufacturer: Vishay; CompType: Resistor; Tolerance_%: 0.1; VDC_V: 200V; TempCo: 25ppm/C; AEC Category: Q200
signal-integrity model Resistor
simulation model Resistor
footprint 0805_HV (0805 with 30mil clearance between pads)
footprint 2010M
footprint 2010L
pins: 1, 2

## TNPW080540K2BEEA
designator R?  value 10k  Power_W: 0.2W  (hidden comment: TNPW080540K2BEEA)
RES 40.2K OHM 0.1% 1/5W 0805; Manufacturer: Vishay; CompType: Resistor; Tolerance_%: 0.1; VDC_V: 200V; TempCo: 25ppm/C; AEC Category: Q200
signal-integrity model Resistor
simulation model Resistor
footprint 0805_HV (0805 with 30mil clearance between pads)
footprint 2010M
footprint 2010L
pins: 1, 2

## TNPW120649R9BEEA
designator R?  value 49.9  Power_W: 0.4W  (hidden comment: TNPW120649R9BEEA)
RES, 49.9  0.1%, 0.4 W, 25 PPM / C, AEC-Q200; Manufacturer: Vishay; CompType: Resistor; Tolerance_%: 0.1; VDC_V: 200V; AEC Category: Q200
signal-integrity model Resistor
simulation model Resistor
footprint 1206_190
footprint 2010M
footprint 2010L
pins: 1, 2

## TNPW0805160RBEEA
designator R?  value 160R  Power_W: 0.2W  (hidden comment: TNPW0805160RBEEA)
RES 160R OHM 0.1% 1/5W 0805; Manufacturer: Vishay; CompType: Resistor; Tolerance_%: 0.1; VDC_V: 200V; TempCo: 25ppm/C; AEC Category: Q200
signal-integrity model Resistor
simulation model Resistor
footprint 0805_HV (0805 with 30mil clearance between pads)
footprint 2010M
footprint 2010L
pins: 1, 2

## UCC5390S
designator U?
Isolated Gate Drivers with High CMTI and Scalable Drive Strength, D0008B (SOIC-8); Manufacturer: Texas Instruments; SymbolCreator: a0411947; SizeArea_mm2: 29.4; SizeAreaWB_mm2: 55.2; SizeX_mm: 6; SizeY_mm: 4.9; SizeZ_mm: 1.75; CompType: IC; U/M: EA
footprint UCC5390S (SOIC, 8-Leads, Body 5.95x7.6mm (max), Pitch 1.27mm)
footprint D0008B_N
footprint D0008B_M
footprint D0008B_L
pins: 1 VCC1 (power), 2 IN+ (in), 3 IN- (in), 4 GND1 (power), 5 VCC2 (power), 6 OUTH (out), 7 OUTL (out), 8 VEE2 (power)

## WASHER SHOULDER - 3065
designator W?, comment 36-3065-ND
WASHER SHOULDER #8 FIBRE
footprint WASHER SHOULDER
pins: 0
